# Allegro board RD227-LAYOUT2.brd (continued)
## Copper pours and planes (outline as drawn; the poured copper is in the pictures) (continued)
SIG341 on TOP: 45.7,11.8 45.66,11.81 45.65,11.85 45.65,12.03 45.65,12.05 45.66,12.06 46.6,13 46.6,13.3 46.61,13.34 46.63,13.37 46.83,13.57 46.86,13.59 46.9,13.6 47,13.6 47.1,13.5 47,13.4 46.94,13.4 46.8,13.26 46.8,12.7 46.8,12.65 46.8,12.45 46.8,12.43 46.79,12.41 46.19,11.81 46.17,11.8 46.15,11.8 45.94,11.8 45.92,11.78 45.84,11.75 45.76,11.8
SIG344 on TOP: 54.05,9.7 53.98,9.73 53.95,9.8 53.95,9.95 53.73,10.17 53.71,10.2 53.7,10.24 53.7,10.68 53.7,10.71 53.72,10.74 53.46,11 53.09,11 53.05,11.01 53.02,11.03 51.63,12.42 51.61,12.45 51.6,12.49 51.6,13.05 51.7,13.15 51.8,13.05 51.8,12.55 53.15,11.2 53.5,11.2 53.57,11.17 53.99,10.75 54.05,10.75 54.12,10.72 54.15,10.65 54.15,10.3 54.52,9.93 54.54,9.9 54.55,9.86 54.55,9.8 54.52,9.73 54.45,9.7
SIG345 on TOP: 52.9,9.65 52.83,9.68 52.8,9.75 52.8,10.01 52.81,10.05 52.83,10.08 52.85,10.1 52.85,10.6 51.13,12.32 51.11,12.35 51.1,12.39 51.1,13.05 51.2,13.15 51.3,13.05 51.3,12.45 52.98,10.77 53.19,10.77 53.26,10.74 53.29,10.67 53.29,10.11 53.47,9.93 53.49,9.9 53.5,9.86 53.5,9.75 53.47,9.68 53.4,9.65
SIG347 on TOP: 51.7,9.9 51.63,9.93 51.6,10 51.6,11.1 50.63,12.07 50.6,12.14 50.6,13.05 50.7,13.15 50.8,13.05 50.8,12.35 52.37,10.78 52.39,10.75 52.4,10.71 52.4,10 52.37,9.93 52.3,9.9
SIG369 on TOP: 46.41,10.25 46.34,10.28 46.31,10.35 46.31,11.48 46.32,11.52 46.34,11.55 47.6,12.81 47.6,13.05 47.7,13.15 47.8,13.05 47.8,12.59 47.79,12.55 47.77,12.52 47.48,12.23 47.45,12.21 47.41,12.2 47.27,12.2 46.64,11.56 46.64,10.81 46.82,10.63 46.84,10.6 46.85,10.56 46.85,10.35 46.82,10.28 46.75,10.25
SIG396 on TOP: 13.35,3.45 13.31,3.46 13.3,3.5 13.3,4.55 13.31,4.59 13.35,4.6 14.05,4.6 14.09,4.59 14.1,4.55 14.1,3.5 14.09,3.46 14.05,3.45
SIG397 on TOP: 12.25,3.85 12.21,3.86 12.2,3.9 12.2,5.2 12.21,5.24 12.25,5.25 12.65,5.25 12.69,5.24 12.7,5.2 12.7,3.9 12.69,3.86 12.65,3.85
SIG423 on BOTTOM: 45,22.05 44.96,22.06 44.95,22.1 44.95,22.5 44.96,22.54 45,22.55 46.3,22.55 46.34,22.54 46.35,22.5 46.35,22.1 46.34,22.06 46.3,22.05
SIG436 on BOTTOM: 28.65,22.35 28.61,22.36 28.6,22.4 28.6,24 28.3,24.3 26.8,24.3 26.76,24.31 26.75,24.35 26.75,26.55 26.76,26.59 26.8,26.6 29.3,26.6 29.34,26.59 29.35,26.55 29.35,23.1 29.55,22.9 29.9,22.9 29.94,22.89 29.95,22.85 29.95,22.4 29.94,22.36 29.9,22.35
SIG437 on BOTTOM: 28.65,20.45 28.61,20.46 28.6,20.5 28.6,21 28.61,21.04 28.65,21.05 29.15,21.05 30.04,21.94 30.05,21.95 30.07,21.95 30.35,21.95 30.65,22.25 30.65,22.85 30.66,22.89 30.7,22.9 31.95,22.9 31.99,22.89 32,22.85 32,22.47 32,22.45 31.99,22.44 31.91,22.36 31.9,22.35 31.88,22.35 31.45,22.35 30.56,21.46 30.55,21.45 30.53,21.45 30.2,21.45 29.9,21.15 29.9,20.5 29.89,20.46 29.85,20.45
SIG438 on BOTTOM: 28.27,19.1 28.25,19.1 28.24,19.11 27.21,20.14 27.2,20.15 27.2,20.17 27.2,23.5 27.05,23.65 26.8,23.65 26.76,23.66 26.75,23.7 26.75,23.95 26.76,23.99 26.8,24 27.55,24 27.59,23.99 27.6,23.95 27.6,20.4 28.45,19.55 31.6,19.55 31.61,19.56 31.75,19.7 31.75,20.2 31.45,20.5 30.65,20.5 30.61,20.51 30.6,20.55 30.6,20.95 30.61,20.99 30.65,21 31.9,21 31.94,20.99 31.95,20.95 31.95,20.7 32.39,20.26 32.4,20.25 32.4,20.23 32.4,19.3 32.39,19.26 32.35,19.25 32.35,19.15 32.34,19.11 32.3,19.1

Small or netless copper shapes (teardrops, artwork), in the pictures only: 43 on TOP, 39 on BOTTOM, 5 on CONDUCTIVE2, 13 on CONDUCTIVE3

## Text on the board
Ref Des/Silkscreen Bottom: UL
Ref Des/Silkscreen Top: 1 | 5 | 10 | 2
SYMBOL-1-TOP: 1 | 5 | 10 | 2
SYMBOL-2-TOP: C206 | C202 | L201 | TP201 | C216 | CN202 | C203 | R204 | C214 | C209 | C204 | Q203 | TP225 | TP227 | TP226 | L202 | IC202 | R226 | Q206 | C233 | C231 | C243 | R230 | R231 | R232 | C223 | TP216 | C229 | R220 | C235 | C238 | R219 | R206 | C226 | TP215 | C211 | C210 | C205 | C201 | CN201 | C212 | C207 | C215 | C208 | C213 | C217 | C220 | C245 | Q204 | C242 | Q205 | C246 | TP221 | C240 | TP220 | R229 | R205 | C247 | C248 | C228 | C225 | C232 | C230 | C227 | C224 | TP214 | L203 | C234 | Q207 | TP213 | C236 | CN203 | C237 | INPUT | 1 | 2 | 5 | CONTROL | 10 | TYPE2 | OUTPUT | BUCK-BOOST
SYMBOL-2-BOTTOM: Q201 | C221 | C222 | R210 | R217 | Q202 | IC201 | C218 | D201 | R203 | R208 | R207 | TP217 | TP218 | TP224 | TP223 | TP222 | D203 | R202 | R213 | R234 | R235 | R214 | R216 | C219 | R211 | R212 | R239 | R236 | R238 | R240 | C253 | R241 | R237 | C254 | C255 | C250 | C249 | TP203 | D208 | D209 | TP204 | TP206 | TP205 | TP234 | TP233 | TP208 | TP232 | ADDR SELECT | CURRENT COMP | VOLTAGE COMP | TP231 | R225 | R222 | R221 | R228 | R227 | FL201 | R224 | TP202 | R223 | R209 | C244 | R201 | C241 | D204 | D202 | D205 | R215 | D206 | D207 | TP219 | C251 | C239 | R233 | C252 | TP207 | TP210 | TP209 | TP211 | TP212 | UL
User.5: UL
